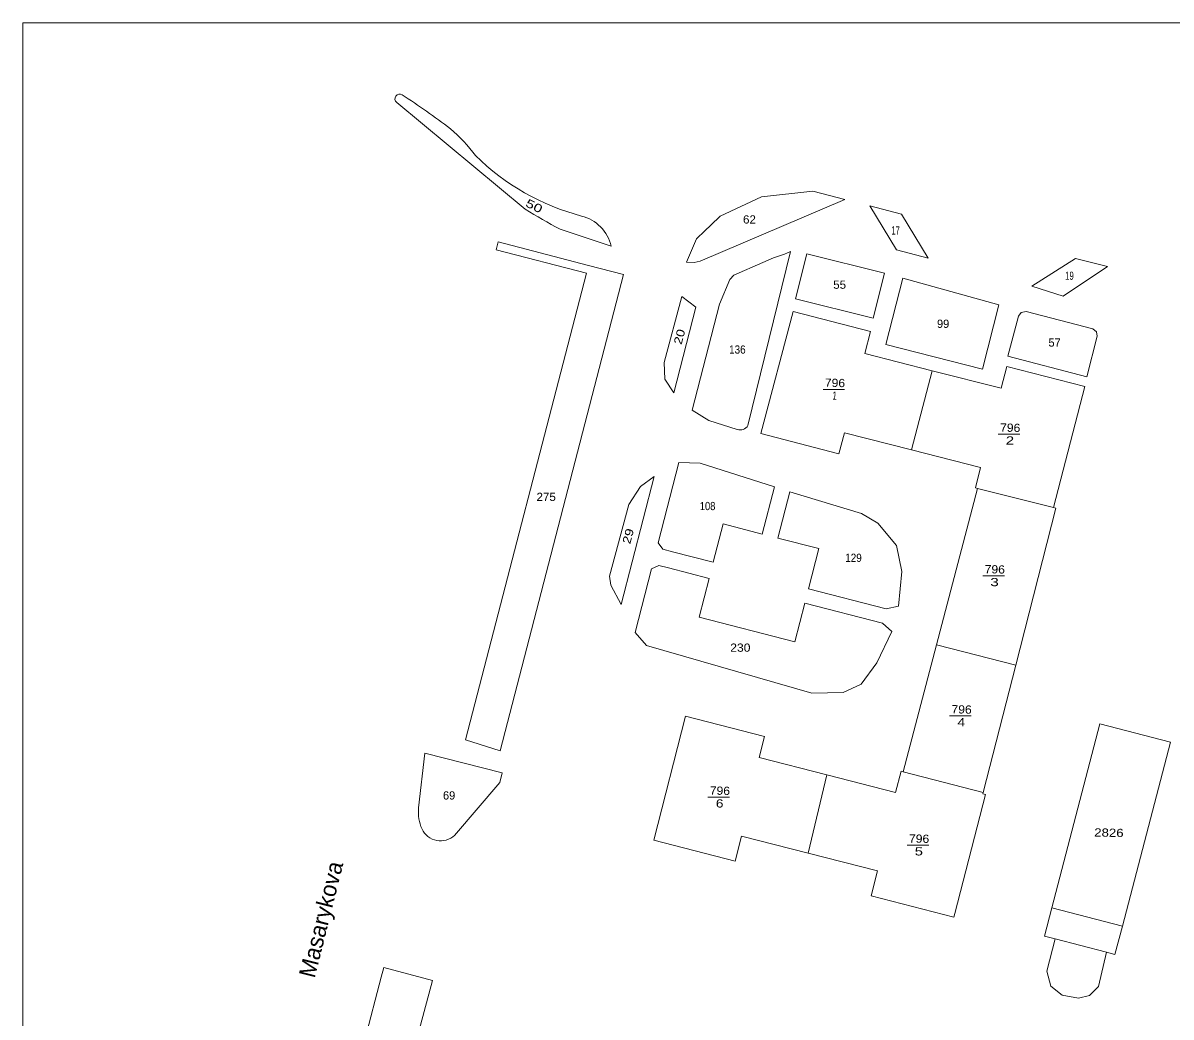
# Model space of a CAD drawing. Extents: x -843398 to -843100, y -1003450 to -1003185.
# Drawn here: x -843398 to -843258.5, y -1003305.4 to -1003184.6 of the extents above; entities that cross this region are included whole.
import ezdxf
from ezdxf.enums import TextEntityAlignment as Align

# ---------------------------------------------------------------- set-up
doc = ezdxf.new("R2010")
doc.units = 0
doc.header["$LTSCALE"] = 0.4
doc.layers.add('20', color=7, linetype='Continuous')
for name, color, linetype, lineweight in [('35', 7, 'Continuous', 13), ('36', 7, 'Continuous', 13), ('38', 7, 'Continuous', 13), ('43', 7, 'Continuous', 13), ('44', 7, 'Continuous', 13)]:
    doc.layers.add(name, color=color, linetype=linetype, lineweight=lineweight)

msp = doc.modelspace()

# ---------------------------------------------------------------- linework, layer by layer
at = {"layer": '35'}
for p, q in [((-843300.757, -1003229.103), (-843298.127, -1003229.103)), ((-843279.471, -1003234.553), (-843276.841, -1003234.553)), ((-843281.343, -1003251.76), (-843278.713, -1003251.76)), ((-843285.376, -1003268.783), (-843282.746, -1003268.783)), ((-843314.736, -1003278.66), (-843312.106, -1003278.66)), ((-843290.537, -1003284.484), (-843287.907, -1003284.484))]:
    msp.add_line(p, q, dxfattribs=at)
at = {"layer": '36'}
msp.add_line((-843272.96, -1003292.11), (-843264.37, -1003294.33), dxfattribs=at)
msp.add_lwpolyline([(-843272.57, -1003295.88), (-843273.57, -1003299.8), (-843273.06, -1003301.6), (-843271.7, -1003302.7), (-843269.73, -1003303.09), (-843268.4, -1003302.76), (-843267.28, -1003301.64), (-843266.33, -1003297.5)], dxfattribs=at)
at = {"layer": '38'}
for points in [[(-843304.37, -1003219.64), (-843308.31, -1003234.45), (-843298.83, -1003236.94), (-843298.16, -1003234.36), (-843289.99, -1003236.45), (-843287.51, -1003226.84), (-843295.66, -1003224.75), (-843294.97, -1003222.05)], [(-843273.85, -1003295.55), (-843272.96, -1003292.11), (-843267.12, -1003269.76), (-843258.54, -1003271.97), (-843264.37, -1003294.33), (-843265.3, -1003297.77), (-843266.33, -1003297.5), (-843272.57, -1003295.88)]]:
    msp.add_lwpolyline(points, close=True, dxfattribs=at)
for points in [[(-843287.51, -1003226.84), (-843279.13, -1003228.97), (-843278.44, -1003226.31), (-843268.95, -1003228.73), (-843272.76, -1003243.47), (-843281.98, -1003241.13), (-843282.25, -1003241.06), (-843281.61, -1003238.59), (-843289.99, -1003236.45)], [(-843272.76, -1003243.47), (-843272.46, -1003243.55), (-843277.33, -1003262.61), (-843286.98, -1003260.16), (-843281.98, -1003241.13)], [(-843286.98, -1003260.16), (-843291.03, -1003275.56), (-843281.28, -1003278.07), (-843277.33, -1003262.61)], [(-843302.54, -1003285.45), (-843310.65, -1003283.37), (-843311.43, -1003286.42), (-843321.32, -1003283.89), (-843317.46, -1003268.82), (-843307.85, -1003271.29), (-843308.5, -1003273.84), (-843300.28, -1003275.95)], [(-843281.28, -1003278.07), (-843281.32, -1003278.24), (-843281.03, -1003278.32), (-843284.74, -1003292.79), (-843284.85, -1003293.22), (-843294.92, -1003290.63), (-843294.15, -1003287.6), (-843302.54, -1003285.45), (-843300.28, -1003275.95), (-843291.94, -1003278.09), (-843291.26, -1003275.5), (-843291.03, -1003275.56)]]:
    msp.add_lwpolyline(points, dxfattribs=at)
at = {"layer": '43'}
for p, q in [((-843336.936, -1003207.218), (-843352.55, -1003194.225)), ((-843326.497, -1003211.692), (-843332.7, -1003209.62)), ((-843340.03, -1003276.85), (-843345.511, -1003283.291))]:
    msp.add_line(p, q, dxfattribs=at)
for points in [[(-843317.35, -1003213.63), (-843316.39, -1003213.66), (-843315.7, -1003213.5), (-843298.119, -1003206.011), (-843301.98, -1003205.01), (-843308.22, -1003205.71), (-843313.24, -1003208.06), (-843314.38, -1003209.15), (-843315.11, -1003209.85), (-843316.12, -1003210.82)], [(-843291.207, -1003207.798), (-843287.975, -1003213.164), (-843291.842, -1003212.141), (-843295.08, -1003206.799)], [(-843340.481, -1003212.151), (-843329.502, -1003214.995), (-843344.198, -1003271.668), (-843339.971, -1003273.013), (-843324.977, -1003215.134), (-843329.252, -1003214.027), (-843340.23, -1003211.183)], [(-843304.089, -1003218.091), (-843302.736, -1003212.645), (-843293.3, -1003214.989), (-843294.653, -1003220.435)], [(-843270.075, -1003213.196), (-843266.196, -1003214.171), (-843271.58, -1003217.769), (-843275.391, -1003216.555)], [(-843293.13, -1003223.64), (-843291.073, -1003215.589), (-843279.396, -1003218.808), (-843281.397, -1003226.638)], [(-843317.916, -1003217.819), (-843316.198, -1003219.095), (-843318.877, -1003229.509), (-843319.981, -1003227.845), (-843320.062, -1003225.837)], [(-843268.71, -1003227.57), (-843267.46, -1003222.65), (-843267.53, -1003222.11), (-843267.98, -1003221.75), (-843276.08, -1003219.62), (-843276.68, -1003219.76), (-843277, -1003220.2), (-843278.29, -1003225.08)], [(-843318.262, -1003238.001), (-843315.68, -1003238.08), (-843306.656, -1003240.947), (-843308.13, -1003246.675), (-843312.89, -1003245.45), (-843314.087, -1003250.103), (-843319.037, -1003248.829), (-843320.2, -1003248.53), (-843320.764, -1003247.725)], [(-843325.271, -1003255.244), (-843326.522, -1003252.904), (-843326.691, -1003251.801), (-843324.353, -1003243.076), (-843322.927, -1003240.886), (-843321.271, -1003239.699)], [(-843304.79, -1003241.54), (-843296.09, -1003244.19), (-843294.11, -1003245.36), (-843291.81, -1003248.07), (-843291.16, -1003251.23), (-843291.59, -1003255.44), (-843293.08, -1003255.77), (-843302.51, -1003253.344), (-843301.25, -1003248.445), (-843306.236, -1003247.162)], [(-843323.575, -1003258.652), (-843321.586, -1003250.921), (-843320.704, -1003250.488), (-843319.54, -1003250.787), (-843314.591, -1003252.06), (-843315.807, -1003256.789), (-843304.167, -1003259.784), (-843302.961, -1003255.096), (-843293.531, -1003257.522), (-843292.385, -1003258.53), (-843294.23, -1003262.32), (-843296.11, -1003264.92), (-843298.32, -1003265.94), (-843302.12, -1003266.03), (-843322.18, -1003260.24)], [(-843361.99, -1003329.7), (-843360.74, -1003325.11), (-843358.69, -1003317.1), (-843356.401, -1003308.145), (-843354.45, -1003300.51), (-843354.102, -1003299.361), (-843348.18, -1003300.92), (-843350.21, -1003308.48), (-843352.01, -1003315.65), (-843353.95, -1003323.11), (-843356.05, -1003331.19)]]:
    msp.add_lwpolyline(points, close=True, dxfattribs=at)
for points in [[(-843305.435, -1003212.681), (-843306.766, -1003213.129), (-843308.072, -1003213.697), (-843311.59, -1003215.22), (-843312.06, -1003215.75), (-843313.347, -1003218.734), (-843316.668, -1003231.638), (-843314.638, -1003232.88), (-843311.188, -1003233.97)], [(-843309.87, -1003233.5), (-843304.704, -1003212.36), (-843305.435, -1003212.681)], [(-843349.888, -1003279.958), (-843349.113, -1003273.305), (-843339.736, -1003275.694), (-843340.03, -1003276.85)]]:
    msp.add_lwpolyline(points, dxfattribs=at)
for centre, radius, start, end in [((-843352.199, -1003193.7827), 0.5647, 57.11768, 231.55717), ((-843399.1906, -1003266.9437), 87.5172, 52.58784, 57.28611), ((-843359.8074, -1003213.3752), 21.0794, 36.97628, 49.15085), ((-843322.6667, -1003180.0323), 28.9676, 225.50805, 255.14795), ((-843293.1458, -1003134.9363), 84.5115, 238.79159, 242.09329), ((-843331.2865, -1003212.801), 4.9163, 13.03616, 75.93466), ((-843310.8393, -1003232.8662), 1.1581, 252.45328, 326.81863), ((-843345.1592, -1003280.5092), 4.7607, 173.35284, 205.07935), ((-843347.2137, -1003281.4707), 2.4923, 205.07935, 313.08696)]:
    msp.add_arc(centre, radius, start, end, dxfattribs=at)
at = {"layer": '44'}
msp.add_lwpolyline([(-843397.952, -1003184.571), (-843099.952, -1003184.571), (-843099.952, -1003394.571), (-843099.952, -1003450.409), (-843397.952, -1003450.409)], close=True, dxfattribs=at)

# ---------------------------------------------------------------- texts
at = {"layer": '20'}
msp.add_text('Masarykova', height=2, rotation=75.959, dxfattribs=at).set_placement((-843362.521, -1003300.731))
at = {"layer": '35'}
for s, width, p in [('796', 1.1, (-843299.3115, -1003228.8058)), ('1', 0.7, (-843299.3465, -1003230.3558)), ('796', 1.1, (-843278.0255, -1003234.2558)), ('2', 1.35, (-843278.059, -1003235.8053)), ('796', 1.1, (-843279.8965, -1003251.4628)), ('3', 1.4, (-843279.9315, -1003253.0125)), ('796', 1.1, (-843283.9305, -1003268.4858)), ('4', 1.25, (-843283.9635, -1003270.0354)), ('796', 1.1, (-843313.2905, -1003278.3628)), ('6', 1.25, (-843313.323, -1003279.9124)), ('796', 1.1, (-843289.0915, -1003284.1868)), ('2826', 1.2, (-843266.0345, -1003283.4665)), ('5', 1.35, (-843289.1245, -1003285.736))]:
    msp.add_text(s, height=1, rotation=358.734, dxfattribs=dict(at, width=width)).set_placement(p, align=Align.CENTER)
at = {"layer": '43'}
for s, height, rotation, width, p in [('50', 0.999, 333.315, 1.4, (-843337.002, -1003206.796)), ('20', 0.999, 75.012, 1.25, (-843317.954, -1003223.729)), ('29', 1, 75.001, 1.25, (-843324.187, -1003247.96))]:
    msp.add_text(s, height=height, rotation=rotation, dxfattribs=dict(at, width=width)).set_placement(p)
for s, width, p in [('62', 1.05, (-843310.473, -1003208.948)), ('17', 0.7, (-843292.459, -1003210.28)), ('19', 0.7, (-843271.332, -1003215.786)), ('55', 1.05, (-843299.516, -1003216.873)), ('136', 0.9, (-843312.164, -1003224.754)), ('275', 1.05, (-843335.559, -1003242.658)), ('108', 0.85, (-843315.725, -1003243.772)), ('129', 0.9, (-843298.057, -1003250.063)), ('230', 1.1, (-843312.027, -1003260.982))]:
    msp.add_text(s, height=1, dxfattribs=dict(at, width=width)).set_placement(p)
for s, p in [('99', (-843286.91, -1003221.626)), ('57', (-843273.365, -1003223.904)), ('69', (-843346.926, -1003278.939))]:
    msp.add_text(s, height=1, dxfattribs=at).set_placement(p)

doc.saveas('drawing.dxf')
